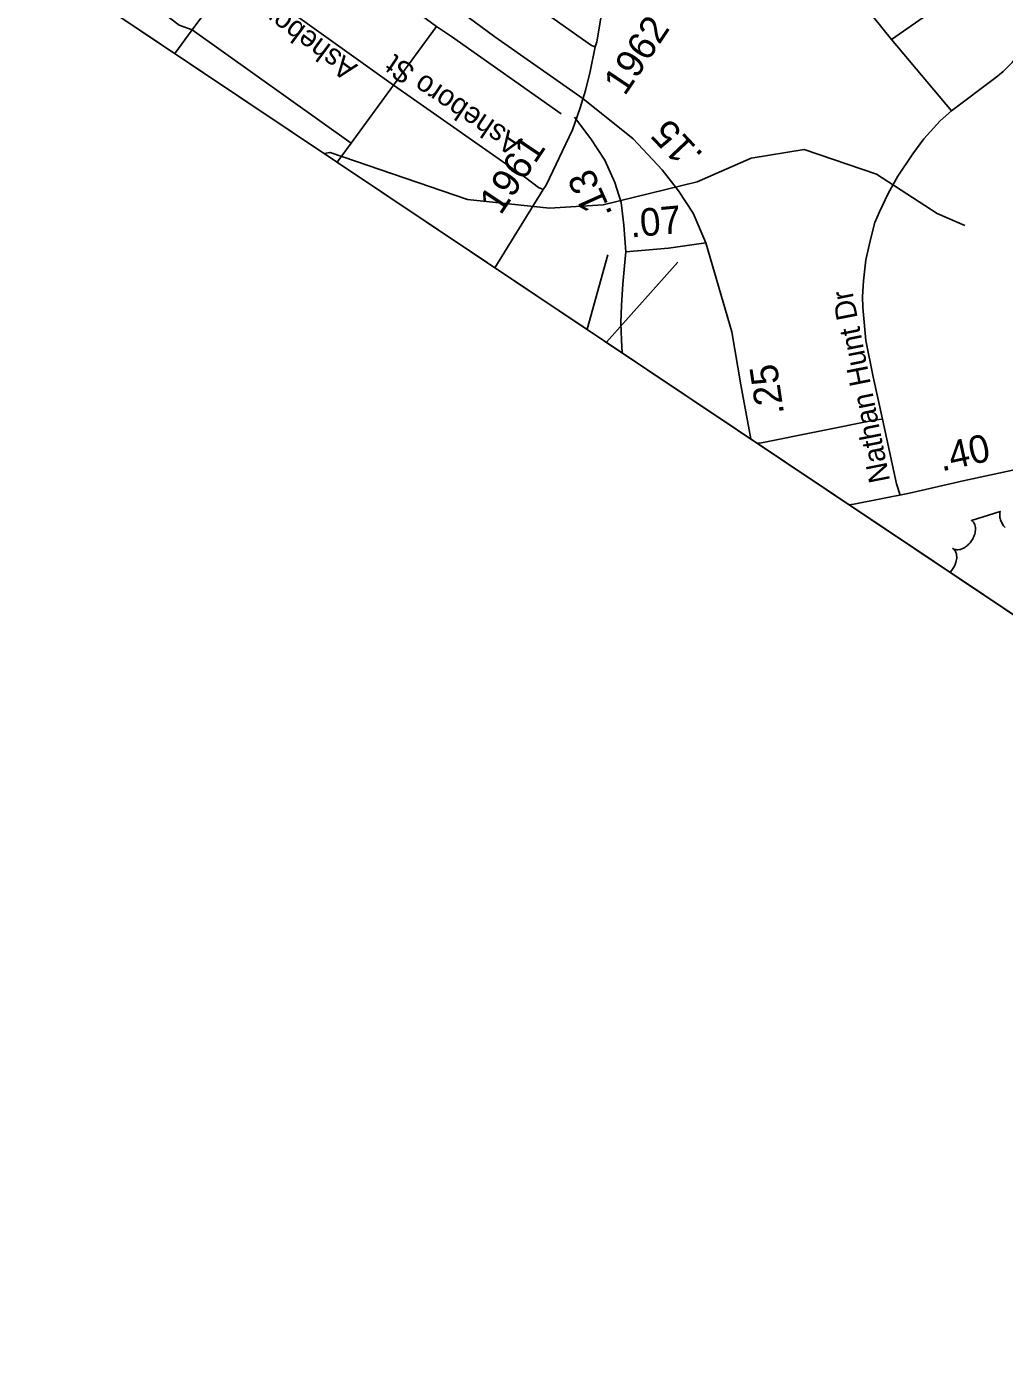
# Model space of a CAD drawing. Extents: x 1715610 to 1720914, y 798298 to 802505.
# Drawn here: x 1715767.3 to 1715863.2, y 799278 to 799408.2 of the extents above; entities that cross this region are included whole.
import ezdxf

# ---------------------------------------------------------------- set-up
doc = ezdxf.new("R2010")
doc.units = 0
doc.layers.add('Default', color=7, linetype='Continuous')
doc.layers.add('Prop DSN Text', color=7, linetype='Continuous')

msp = doc.modelspace()

# ---------------------------------------------------------------- linework, layer by layer
at = {"layer": 'Default'}
for p, q in [((1715610.03, 799520.5), (1715972.32, 799278.02)), ((1715610.03, 799520.5), (1715972.32, 799278.02)), ((1715783.53, 799407.82), (1715787.78, 799413.54)), ((1715781.84, 799405.51), (1715783.53, 799407.82)), ((1715783.53, 799407.82), (1715799.14, 799396.7)), ((1715803.28, 799402.38), (1715807.52, 799408.15)), ((1715852.16, 799406.88), (1715858.05, 799399.88)), ((1715799.14, 799396.7), (1715803.28, 799402.38)), ((1715797.76, 799394.85), (1715799.14, 799396.7)), ((1715813.25, 799384.48), (1715817.99, 799392.14)), ((1715822.29, 799378.44), (1715824.34, 799385.75)), ((1715831.2, 799385.02), (1715824.19, 799377.16)), ((1715857.9, 799354.6), (1715866.06, 799349.14))]:
    msp.add_line(p, q, dxfattribs=at)
for points in [[(1715821.88, 799401.1), (1715813.24, 799407.13), (1715801.54, 799415.8), (1715796, 799420.28), (1715793.69, 799422.27), (1715788.38, 799427.42), (1715785.59, 799429.91), (1715783.38, 799431.61), (1715779.49, 799434.84), (1715773.6, 799439.71), (1715771.73, 799441.17)], [(1715852.16, 799406.88), (1715856.45, 799409.86), (1715857.25, 799410.73), (1715858.01, 799411.85), (1715858.48, 799412.86), (1715858.69, 799413.45), (1715858.79, 799414.13), (1715858.87, 799415.23), (1715858.95, 799418.97), (1715859.09, 799421.15), (1715859.29, 799422.95), (1715859.75, 799425.85)], [(1715858.05, 799399.88), (1715862.4, 799403.15), (1715863.11, 799403.75), (1715864.02, 799404.63), (1715865.23, 799406.14), (1715865.81, 799407.07), (1715866.35, 799408.23), (1715866.9, 799409.71), (1715867.31, 799411.41), (1715867.61, 799413.39), (1715867.81, 799416.16), (1715867.93, 799421.81), (1715868.36, 799424.19)], [(1715792.73, 799419.5), (1715795.2, 799417.2), (1715796.97, 799415.68), (1715798.26, 799414.68), (1715804.69, 799410.2), (1715807.52, 799408.15)], [(1715808.51, 799416.35), (1715822.74, 799406.28), (1715823.09, 799406.16)], [(1715787.78, 799413.54), (1715788.21, 799413.17), (1715790.94, 799411.26), (1715803.28, 799402.38)], [(1715823.09, 799406.16), (1715823.24, 799406.66), (1715824.49, 799414.04)], [(1715773.96, 799410.78), (1715775.2, 799412.41), (1715775.8, 799413.1), (1715775.98, 799413.09), (1715782.25, 799408.28), (1715783.53, 799407.82)], [(1715846.87, 799413.23), (1715850.39, 799409.08), (1715852.16, 799406.88)], [(1715807.52, 799408.15), (1715809, 799407.16), (1715819.75, 799399.59)], [(1715821.6, 799400.17), (1715822.13, 799401.88), (1715822.6, 799403.73), (1715823.09, 799406.16)], [(1715803.28, 799402.38), (1715816.27, 799393.29), (1715817.54, 799392.34), (1715817.99, 799392.14)], [(1715833.93, 799386.91), (1715832.71, 799389.82), (1715831.27, 799392.02), (1715829.66, 799394.1), (1715826.8, 799397.13), (1715821.88, 799401.1)], [(1715817.99, 799392.14), (1715818.29, 799392.58), (1715820.86, 799398.01), (1715821.6, 799400.17)], [(1715821.07, 799399.26), (1715822.67, 799397.13), (1715824.04, 799395.02), (1715825.02, 799392.83), (1715825.64, 799390.87), (1715825.91, 799388.65), (1715826.09, 799386.03)], [(1715851.28, 799369.61), (1715850.35, 799373.77), (1715849.66, 799377.35), (1715849.35, 799380.58), (1715849.32, 799381.67), (1715849.4, 799383.19), (1715849.64, 799385.24), (1715850.09, 799387.25), (1715850.52, 799388.92), (1715850.98, 799389.97), (1715851.85, 799391.76), (1715852.79, 799393.45), (1715854.25, 799395.66), (1715855.35, 799397.14), (1715856.95, 799398.91), (1715858.05, 799399.88)], [(1715859.36, 799388.61), (1715856.63, 799389.81), (1715850.7, 799393.65), (1715843.6, 799396.07), (1715838.39, 799395.24), (1715833.11, 799392.91), (1715823.87, 799390.66), (1715818.59, 799390.33), (1715810.57, 799391.19), (1715797.07, 799395.8), (1715796.5, 799395.69)], [(1715826.09, 799386.03), (1715830.27, 799386.41), (1715833.93, 799386.91)], [(1715838.36, 799367.68), (1715837.38, 799372.97), (1715836.48, 799378.2), (1715833.93, 799386.91)], [(1715826.09, 799386.03), (1715825.95, 799384.67), (1715825.79, 799382.85), (1715825.68, 799380.79), (1715825.59, 799379.06), (1715825.68, 799377.36), (1715825.73, 799376.13)], [(1715839, 799367.25), (1715839.4, 799367.31), (1715850.61, 799369.56), (1715851.28, 799369.61)], [(1715853.01, 799362.17), (1715852.67, 799363.28), (1715851.28, 799369.61)], [(1715873.01, 799366.37), (1715871.72, 799366.19), (1715870.47, 799365.88), (1715864.35, 799364.69), (1715859.19, 799363.55), (1715853.92, 799362.37), (1715848.46, 799361.29), (1715848.02, 799361.21)], [(1715863.32, 799358.98), (1715863.25, 799359.06), (1715863.17, 799359.15), (1715863.06, 799359.31), (1715863.01, 799359.4), (1715862.95, 799359.5), (1715862.91, 799359.6), (1715862.87, 799359.71), (1715862.85, 799359.79), (1715862.83, 799359.88), (1715862.81, 799359.98), (1715862.8, 799360.07), (1715862.79, 799360.26), (1715862.8, 799360.38), (1715862.82, 799360.52), (1715862.83, 799360.57), (1715860.01, 799359.68), (1715860.07, 799359.64), (1715860.13, 799359.58), (1715860.2, 799359.51), (1715860.25, 799359.43), (1715860.3, 799359.35), (1715860.33, 799359.26), (1715860.37, 799359.12), (1715860.39, 799358.98), (1715860.4, 799358.88), (1715860.4, 799358.74), (1715860.38, 799358.58), (1715860.36, 799358.46), (1715860.33, 799358.33), (1715860.28, 799358.19), (1715860.24, 799358.09), (1715860.18, 799357.97), (1715860.13, 799357.87), (1715860.07, 799357.77), (1715860, 799357.66), (1715859.94, 799357.58), (1715859.87, 799357.48), (1715859.78, 799357.39), (1715859.7, 799357.3), (1715859.61, 799357.21), (1715859.51, 799357.14), (1715859.43, 799357.08), (1715859.35, 799357.02), (1715859.17, 799356.92), (1715858.99, 799356.85), (1715858.92, 799356.83), (1715858.84, 799356.81), (1715858.68, 799356.79), (1715858.58, 799356.79), (1715858.47, 799356.81), (1715858.4, 799356.82), (1715858.33, 799356.84), (1715858.27, 799356.87), (1715858.18, 799356.93), (1715858.28, 799356.85), (1715858.32, 799356.8), (1715858.41, 799356.68), (1715858.44, 799356.62), (1715858.48, 799356.54), (1715858.53, 799356.4), (1715858.55, 799356.23), (1715858.56, 799356.12), (1715858.56, 799355.99), (1715858.54, 799355.83), (1715858.51, 799355.7), (1715858.48, 799355.56), (1715858.44, 799355.44), (1715858.33, 799355.2), (1715858.22, 799354.99), (1715858.09, 799354.81), (1715857.95, 799354.64), (1715857.9, 799354.6)]]:
    msp.add_lwpolyline(points, dxfattribs=at)
at = {"layer": 'Prop DSN Text'}
msp.add_lwpolyline([(1715972.32, 799278.02), (1716250.51, 799693.66), (1715888.23, 799936.14), (1715610.03, 799520.5)], close=True, dxfattribs=at)

# ---------------------------------------------------------------- texts
at = {"layer": 'Default'}
for s, height, rotation, p in [('Asheboro St', 2.0663, 143.4594, (1715799.87, 799404.33)), ('1962', 2.719, 56.2051, (1715825.99, 799401.26)), ('Asheboro St', 2.0663, 146.2051, (1715816.04, 799397.05)), ('.15', 2.719, 133.3783, (1715833.8, 799395.6)), ('1961', 2.719, 56.2051, (1715813.81, 799389.56)), ('.13', 2.719, 114.0645, (1715824.83, 799389.76)), ('.07', 2.719, 5.2818, (1715826.6, 799387.44)), ('Nathan Hunt Dr', 2.0663, 101.2217, (1715852.03, 799363.58)), ('.25', 2.719, 98.489, (1715841.63, 799370.17)), ('.40', 2.719, 12.4148, (1715857.09, 799364.48))]:
    msp.add_text(s, height=height, rotation=rotation, dxfattribs=at).set_placement(p)

doc.saveas('drawing.dxf')
